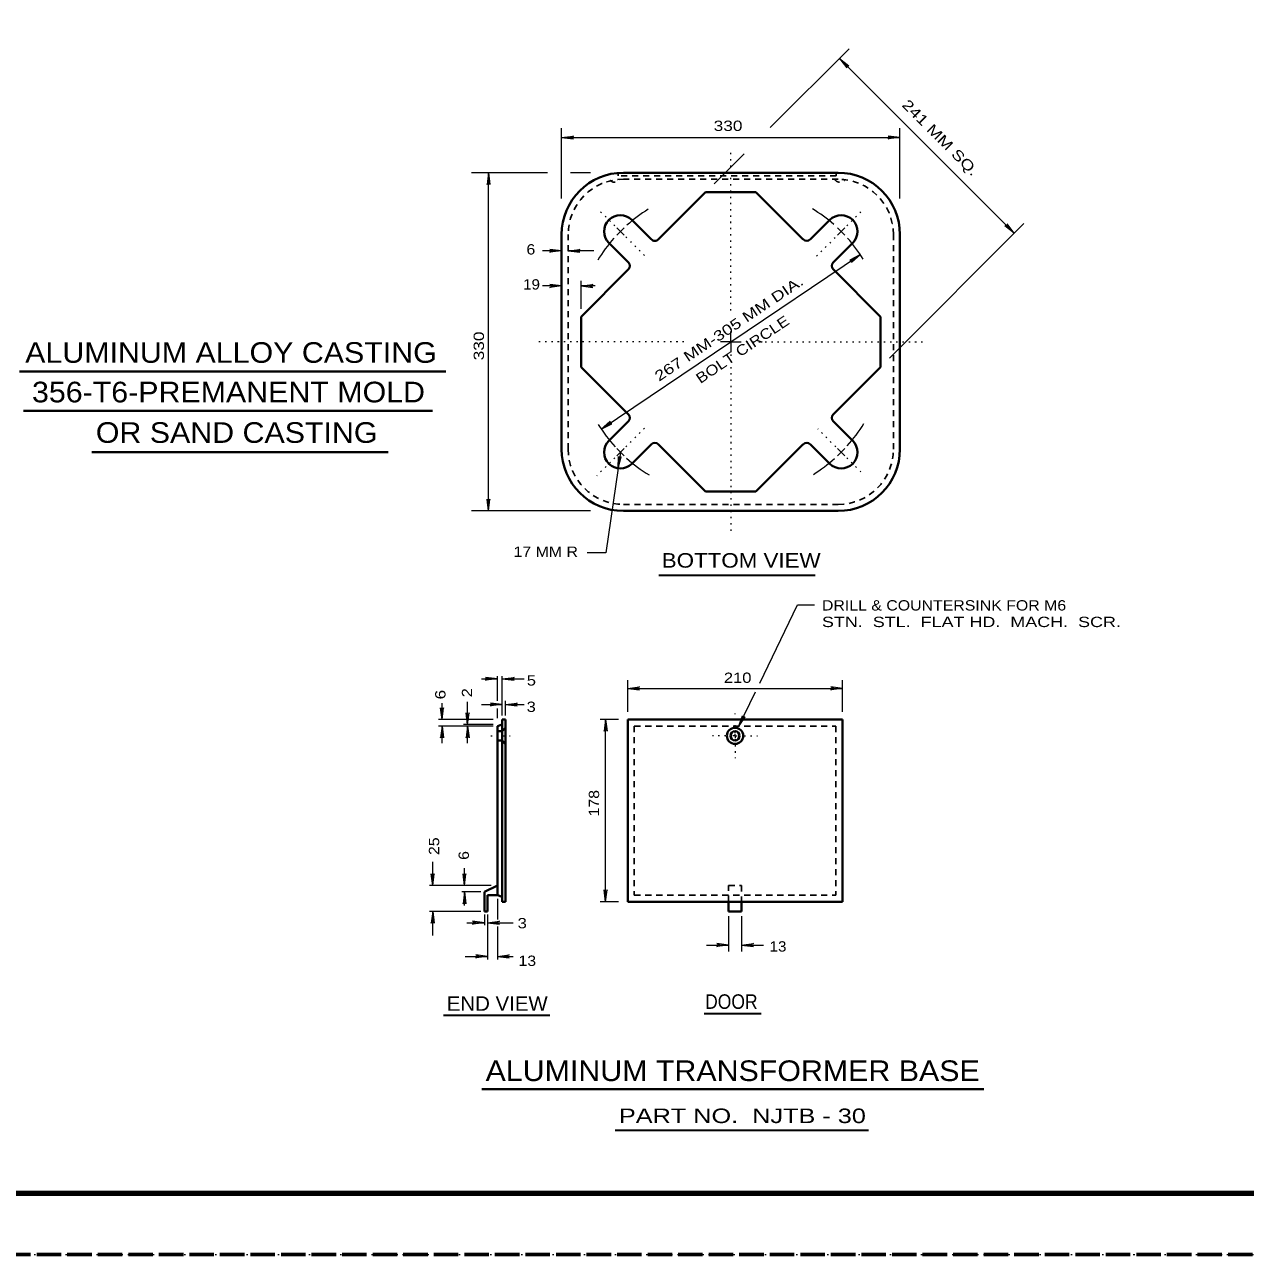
# Model space of a CAD drawing. Extents: x 312583 to 312854, y 144419 to 144597.
# Drawn here: x 312628.6 to 312718.5, y 144418.6 to 144509.2 of the extents above; entities that cross this region are included whole.
import ezdxf
from ezdxf.enums import TextEntityAlignment as Align

# ---------------------------------------------------------------- set-up
doc = ezdxf.new("R2010")
doc.units = 0
doc.header["$LTSCALE"] = 0.3
for name, pattern in [('DOTTED', [1.5, 0.3, -1.2]), ('LONG_DASHED', [7.5, 6, -1.5]), ('SHORT_DASHED', [2.7, 1.5, -1.2])]:
    doc.linetypes.add(name, pattern=pattern)
for name, color, linetype, lineweight in [('1', 7, 'Continuous', 40), ('2', 7, 'Continuous', 13), ('63', 7, 'DOTTED', 13)]:
    doc.layers.add(name, color=color, linetype=linetype, lineweight=lineweight)

msp = doc.modelspace()

# ---------------------------------------------------------------- linework, layer by layer
at = {"layer": '1', "linetype": 'SHORT_DASHED', "lineweight": 25}
for p, q in [((312672.2823, 144498.025), (312672.2823, 144498.2626)), ((312688.3363, 144498.025), (312688.3363, 144498.2626)), ((312688.3363, 144498.025), (312672.2823, 144498.025)), ((312688.482, 144497.7873), (312672.6656, 144497.7873)), ((312668.5946, 144477.9), (312668.5946, 144493.7086)), ((312692.553, 144477.9), (312692.553, 144493.7086)), ((312672.6656, 144473.829), (312688.482, 144473.829)), ((312673.463, 144457.499), (312673.463, 144445.0406)), ((312680.409, 144445.7613), (312681.3673, 144445.7613)), ((312680.409, 144444.5653), (312680.409, 144445.7613)), ((312681.3673, 144445.7613), (312681.3673, 144444.5653)), ((312673.463, 144445.0406), (312688.3133, 144445.0406))]:
    msp.add_line(p, q, dxfattribs=at)
at = {"layer": '1'}
for p, q in [((312688.482, 144498.2626), (312672.6656, 144498.2626)), ((312675.257, 144493.3636), (312678.7146, 144496.829)), ((312678.7146, 144496.829), (312682.4253, 144496.829)), ((312685.8906, 144493.3636), (312682.4253, 144496.829)), ((312673.2866, 144494.782), (312674.7126, 144493.3636)), ((312687.861, 144494.782), (312686.435, 144493.3636)), ((312668.1116, 144477.9), (312668.1116, 144493.7086)), ((312693.0283, 144477.9), (312693.0283, 144493.7086)), ((312671.5923, 144493.0876), (312673.0183, 144491.6693)), ((312689.5553, 144493.0876), (312688.1293, 144491.6693)), ((312669.553, 144487.6596), (312673.0183, 144491.125)), ((312691.5946, 144487.6596), (312688.1293, 144491.125)), ((312669.553, 144487.6596), (312669.553, 144483.949)), ((312691.5946, 144487.6596), (312691.5946, 144483.949)), ((312673.0183, 144480.4836), (312669.553, 144483.949)), ((312688.1293, 144480.4836), (312691.5946, 144483.949)), ((312671.5923, 144478.521), (312673.0183, 144479.947)), ((312689.5553, 144478.521), (312688.1293, 144479.9393)), ((312673.2866, 144476.8266), (312674.7126, 144478.2526)), ((312678.7146, 144474.7873), (312675.2493, 144478.2526)), ((312682.4253, 144474.7873), (312685.8906, 144478.245)), ((312687.861, 144476.8266), (312686.435, 144478.245)), ((312678.7146, 144474.7873), (312682.4253, 144474.7873)), ((312672.6656, 144473.346), (312688.482, 144473.346)), ((312663.3813, 144457.499), (312663.7416, 144457.6216)), ((312663.3813, 144445.0406), (312663.3813, 144457.499)), ((312663.9793, 144457.982), (312663.7416, 144457.982)), ((312663.7416, 144444.5653), (312663.7416, 144457.982)), ((312663.7416, 144457.1233), (312663.9793, 144457.384)), ((312663.9793, 144444.5653), (312663.9793, 144457.982)), ((312672.98, 144457.982), (312688.7963, 144457.982)), ((312672.98, 144457.982), (312672.98, 144444.5653)), ((312688.7963, 144457.982), (312688.7963, 144444.5653)), ((312663.7416, 144457.1233), (312663.3813, 144457.1233)), ((312663.734, 144456.4486), (312663.3813, 144456.4486)), ((312663.734, 144456.4486), (312663.9793, 144456.1803)), ((312662.423, 144445.286), (312663.3813, 144445.7613)), ((312662.423, 144443.8446), (312662.423, 144445.286)), ((312663.3813, 144445.0406), (312662.6606, 144445.0406)), ((312662.6606, 144443.8446), (312662.6606, 144445.0406)), ((312663.3813, 144445.0406), (312663.7416, 144444.9256)), ((312662.6606, 144443.8446), (312662.423, 144443.8446)), ((312663.9793, 144444.5653), (312663.7416, 144444.5653)), ((312672.98, 144444.5653), (312688.7963, 144444.5653)), ((312680.409, 144444.5653), (312680.409, 144443.8446)), ((312680.409, 144443.8446), (312681.3673, 144443.8446)), ((312681.3673, 144444.5653), (312681.3673, 144443.8446))]:
    msp.add_line(p, q, dxfattribs=at)
at = {"layer": '1', "linetype": 'DOTTED', "lineweight": 13}
msp.add_line((312662.8983, 144456.7783), (312664.3243, 144456.7783), dxfattribs=at)
at = {"layer": '1', "lineweight": 158}
msp.add_line((312616.5, 144423.0846), (312849, 144423.0846), dxfattribs=at)
at = {"layer": '1', "linetype": 'LONG_DASHED', "lineweight": 60}
msp.add_line((312851.75, 144418.5846), (312583.526, 144418.5846), dxfattribs=at)
at = {"layer": '1', "linetype": 'SHORT_DASHED', "lineweight": 25}
msp.add_lwpolyline([(312673.463, 144457.499), (312688.3133, 144457.499), (312688.3133, 144445.0406)], dxfattribs=at)
at = {"layer": '1'}
for radius in [0.599, 0.3369]:
    msp.add_circle((312680.8862, 144456.7841), radius, dxfattribs=at)
for centre, radius, start, end in [((312672.6656, 144493.7125), 4.5521, 90, 180), ((312688.4781, 144493.7125), 4.5521, 0, 90), ((312672.4395, 144493.9386), 1.1979, 45, 225), ((312688.7043, 144493.9386), 1.1979, 315, 135), ((312674.982, 144493.6326), 0.3833, 225, 315.01642), ((312686.1628, 144493.6336), 0.3833, 225, 315), ((312672.7445, 144491.3971), 0.3833, 315, 45), ((312688.3992, 144491.3971), 0.3833, 135, 225), ((312672.7445, 144480.2153), 0.3833, 315, 45), ((312688.4003, 144480.2142), 0.3833, 135.01744, 225), ((312672.4395, 144477.6738), 1.1979, 135, 315), ((312674.981, 144477.9789), 0.3833, 45, 135), ((312686.1638, 144477.9778), 0.3833, 45, 134.98307), ((312688.7043, 144477.6738), 1.1979, 225, 45), ((312672.6656, 144477.9), 4.5521, 180, 270), ((312688.4781, 144477.9), 4.5521, 270, 0)]:
    msp.add_arc(centre, radius, start, end, dxfattribs=at)
at = {"layer": '1', "linetype": 'SHORT_DASHED', "lineweight": 25}
for centre, radius, start, end in [((312672.6656, 144493.7125), 4.0729, 90, 180), ((312672.0061, 144498.0336), 0.4681, 222.5149, 327.98151), ((312688.6125, 144498.0336), 0.4681, 212.01849, 317.4851), ((312688.4781, 144493.7125), 4.0729, 0, 90), ((312672.6656, 144477.9), 4.0729, 180, 270), ((312688.4781, 144477.9), 4.0729, 270, 0)]:
    msp.add_arc(centre, radius, start, end, dxfattribs=at)
at = {"layer": '1', "lineweight": 13}
for start, end in [(121.91529, 131.69697), (48.74664, 58.47945), (138.46762, 148.47945), (31.91529, 41.61454), (211.91586, 222.30128), (318.2176, 328.47945), (228.10873, 238.48383), (301.91529, 311.69697)]:
    msp.add_arc((312680.5719, 144485.8062), 11.501, start, end, dxfattribs=at)
at = {"layer": '2'}
for p, q in [((312683.4756, 144501.59), (312689.287, 144507.3936)), ((312688.574, 144506.6806), (312701.454, 144493.8083)), ((312688.574, 144506.6806), (312689.1106, 144505.9983)), ((312688.574, 144506.6806), (312689.264, 144506.144)), ((312689.1106, 144505.9983), (312688.9956, 144506.2666)), ((312689.264, 144506.144), (312688.9956, 144506.2666)), ((312668.1116, 144496.3536), (312668.1116, 144501.5363)), ((312668.1116, 144500.8616), (312668.978, 144500.969)), ((312668.1116, 144500.8616), (312693.0283, 144500.8616)), ((312668.1116, 144500.8616), (312668.978, 144500.7543)), ((312668.978, 144500.969), (312668.702, 144500.8616)), ((312668.978, 144500.7543), (312668.702, 144500.8616)), ((312692.162, 144500.969), (312692.438, 144500.8616)), ((312693.0283, 144500.8616), (312692.162, 144500.969)), ((312692.162, 144500.7543), (312692.438, 144500.8616)), ((312693.0283, 144500.8616), (312692.162, 144500.7543)), ((312693.0283, 144496.3536), (312693.0283, 144501.5363)), ((312679.3433, 144497.45), (312681.559, 144499.6656)), ((312667.0766, 144498.2626), (312661.48, 144498.2626)), ((312662.7296, 144498.2626), (312662.6223, 144497.3963)), ((312662.7296, 144473.346), (312662.7296, 144498.2626)), ((312662.7296, 144498.2626), (312662.837, 144497.3963)), ((312670.2506, 144498.2626), (312668.771, 144498.2626)), ((312662.6223, 144497.3963), (312662.7296, 144497.6723)), ((312662.837, 144497.3963), (312662.7296, 144497.6723)), ((312692.2616, 144484.616), (312702.1593, 144494.5136)), ((312700.9173, 144494.4906), (312701.0323, 144494.2223)), ((312701.454, 144493.8083), (312700.9173, 144494.4906)), ((312672.4433, 144493.9386), (312672.1673, 144494.207)), ((312672.4433, 144493.9386), (312672.1673, 144493.6626)), ((312672.4433, 144493.9386), (312672.7116, 144494.207)), ((312672.4433, 144493.9386), (312672.7116, 144493.6626)), ((312688.7043, 144493.9386), (312688.436, 144494.207)), ((312688.7043, 144493.9386), (312688.436, 144493.6626)), ((312688.7043, 144493.9386), (312688.9803, 144494.207)), ((312688.7043, 144493.9386), (312688.9803, 144493.6626)), ((312700.764, 144494.345), (312701.0323, 144494.2223)), ((312701.454, 144493.8083), (312700.764, 144494.345)), ((312668.1116, 144492.5126), (312666.701, 144492.5126)), ((312667.2453, 144492.62), (312667.5213, 144492.5126)), ((312668.1116, 144492.5126), (312667.2453, 144492.62)), ((312667.2453, 144492.4053), (312667.5213, 144492.5126)), ((312668.1116, 144492.5126), (312667.2453, 144492.4053)), ((312668.5946, 144492.5126), (312669.461, 144492.62)), ((312670.496, 144492.5126), (312668.5946, 144492.5126)), ((312668.5946, 144492.5126), (312669.461, 144492.4053)), ((312669.461, 144492.62), (312669.185, 144492.5126)), ((312669.461, 144492.4053), (312669.185, 144492.5126)), ((312671.0326, 144479.3796), (312690.115, 144492.229)), ((312690.115, 144492.229), (312689.333, 144491.8303)), ((312689.333, 144491.8303), (312689.6243, 144491.8993)), ((312690.115, 144492.229), (312689.4556, 144491.654)), ((312689.4556, 144491.654), (312689.6243, 144491.8993)), ((312667.2453, 144490.0286), (312667.5213, 144489.9213)), ((312668.1116, 144489.9213), (312667.2453, 144490.0286)), ((312669.553, 144488.2346), (312669.553, 144490.297)), ((312669.553, 144489.9213), (312670.4193, 144490.0286)), ((312670.4193, 144490.0286), (312670.1433, 144489.9213)), ((312668.1116, 144489.9213), (312666.701, 144489.9213)), ((312667.2453, 144489.814), (312667.5213, 144489.9213)), ((312668.1116, 144489.9213), (312667.2453, 144489.814)), ((312670.5803, 144489.9213), (312669.553, 144489.9213)), ((312669.553, 144489.9213), (312670.4193, 144489.814)), ((312670.4193, 144489.814), (312670.1433, 144489.9213)), ((312680.57, 144485.8043), (312680.57, 144486.571)), ((312680.57, 144485.8043), (312679.8033, 144485.8043)), ((312680.57, 144485.8043), (312681.3366, 144485.8043)), ((312680.57, 144485.8043), (312680.57, 144485.0376)), ((312671.0326, 144479.3796), (312671.692, 144479.9546)), ((312671.0326, 144479.3796), (312671.8146, 144479.7783)), ((312671.692, 144479.9546), (312671.5233, 144479.7093)), ((312671.8146, 144479.7783), (312671.5233, 144479.7093)), ((312672.4433, 144477.67), (312671.3776, 144470.2563)), ((312672.4433, 144477.67), (312672.1673, 144477.946)), ((312672.4433, 144477.67), (312672.1673, 144477.4016)), ((312672.267, 144476.4893), (312672.29, 144477.3556)), ((312672.267, 144476.4893), (312672.497, 144477.325)), ((312672.29, 144477.3556), (312672.3513, 144477.072)), ((312672.497, 144477.325), (312672.3513, 144477.072)), ((312672.4433, 144477.67), (312672.7116, 144477.946)), ((312672.4433, 144477.67), (312672.7116, 144477.4016)), ((312688.7043, 144477.67), (312688.436, 144477.946)), ((312688.7043, 144477.67), (312688.436, 144477.4016)), ((312688.7043, 144477.67), (312688.9803, 144477.946)), ((312688.7043, 144477.67), (312688.9803, 144477.4016)), ((312662.6223, 144474.2123), (312662.7296, 144473.9363)), ((312662.7296, 144473.346), (312662.6223, 144474.2123)), ((312662.837, 144474.2123), (312662.7296, 144473.9363)), ((312662.7296, 144473.346), (312662.837, 144474.2123)), ((312670.2506, 144473.346), (312661.48, 144473.346)), ((312671.3776, 144470.2563), (312669.9823, 144470.2563)), ((312682.7115, 144460.6593), (312685.492, 144466.423)), ((312685.492, 144466.423), (312686.7493, 144466.423)), ((312662.216, 144460.9796), (312663.3813, 144460.9796)), ((312662.515, 144461.087), (312662.791, 144460.9796)), ((312663.3813, 144460.9796), (312662.515, 144461.087)), ((312662.515, 144460.8723), (312662.791, 144460.9796)), ((312663.3813, 144460.9796), (312662.515, 144460.8723)), ((312663.3813, 144459.362), (312663.3813, 144461.1866)), ((312663.7416, 144458.2886), (312663.7416, 144461.1866)), ((312663.7416, 144460.9796), (312664.608, 144461.087)), ((312663.7416, 144460.9796), (312665.3593, 144460.9796)), ((312663.7416, 144460.9796), (312664.608, 144460.8723)), ((312664.608, 144461.087), (312664.332, 144460.9796)), ((312664.608, 144460.8723), (312664.332, 144460.9796)), ((312672.98, 144458.5493), (312672.98, 144460.8723)), ((312672.98, 144460.2743), (312673.8463, 144460.3816)), ((312672.98, 144460.2743), (312688.7963, 144460.2743)), ((312672.98, 144460.2743), (312673.8463, 144460.167)), ((312673.8463, 144460.3816), (312673.5703, 144460.2743)), ((312673.8463, 144460.167), (312673.5703, 144460.2743)), ((312687.93, 144460.3816), (312688.206, 144460.2743)), ((312688.7963, 144460.2743), (312687.93, 144460.3816)), ((312687.93, 144460.167), (312688.206, 144460.2743)), ((312688.7963, 144460.2743), (312687.93, 144460.167)), ((312688.7963, 144458.5493), (312688.7963, 144460.8723)), ((312659.3103, 144457.982), (312659.3103, 144459.178)), ((312661.1886, 144457.6216), (312661.1886, 144459.293)), ((312662.8753, 144459.201), (312663.1513, 144459.0936)), ((312663.7416, 144459.0936), (312662.8753, 144459.201)), ((312663.9793, 144458.2886), (312663.9793, 144459.362)), ((312663.9793, 144459.0936), (312664.8456, 144459.201)), ((312664.8456, 144459.201), (312664.5696, 144459.0936)), ((312681.145, 144457.4453), (312682.3998, 144460.0191)), ((312659.203, 144458.8483), (312659.3103, 144458.5723)), ((312659.3103, 144457.982), (312659.203, 144458.8483)), ((312659.4176, 144458.8483), (312659.3103, 144458.5723)), ((312659.3103, 144457.982), (312659.4176, 144458.8483)), ((312661.0813, 144458.488), (312661.1886, 144458.212)), ((312661.1886, 144457.6216), (312661.0813, 144458.488)), ((312661.296, 144458.488), (312661.1886, 144458.212)), ((312661.1886, 144457.6216), (312661.296, 144458.488)), ((312662.216, 144459.0936), (312663.7416, 144459.0936)), ((312662.8753, 144458.9863), (312663.1513, 144459.0936)), ((312663.7416, 144459.0936), (312662.8753, 144458.9863)), ((312663.3813, 144458.0816), (312663.3813, 144458.7946)), ((312663.9793, 144459.0936), (312665.3593, 144459.0936)), ((312663.9793, 144459.0936), (312664.8456, 144458.9863)), ((312664.8456, 144458.9863), (312664.5696, 144459.0936)), ((312681.145, 144457.4453), (312681.4286, 144458.2656)), ((312681.4286, 144458.2656), (312681.4056, 144457.9743)), ((312663.0823, 144457.982), (312659.042, 144457.982)), ((312663.0823, 144457.499), (312659.042, 144457.499)), ((312659.3103, 144457.499), (312659.203, 144456.6326)), ((312659.3103, 144456.2493), (312659.3103, 144457.499)), ((312659.3103, 144457.499), (312659.4176, 144456.6326)), ((312663.0823, 144457.6216), (312660.8743, 144457.6216)), ((312661.1886, 144457.499), (312661.0813, 144456.6326)), ((312661.1886, 144456.2493), (312661.1886, 144457.499)), ((312661.1886, 144457.499), (312661.296, 144456.6326)), ((312672.313, 144457.982), (312670.9406, 144457.982)), ((312671.3546, 144457.982), (312671.2473, 144457.1156)), ((312671.2473, 144457.1156), (312671.3546, 144457.3916)), ((312671.3546, 144444.5653), (312671.3546, 144457.982)), ((312671.3546, 144457.982), (312671.462, 144457.1156)), ((312671.462, 144457.1156), (312671.3546, 144457.3916)), ((312681.145, 144457.4453), (312681.6203, 144458.1736)), ((312681.6203, 144458.1736), (312681.4056, 144457.9743)), ((312659.203, 144456.6326), (312659.3103, 144456.9086)), ((312659.4176, 144456.6326), (312659.3103, 144456.9086)), ((312661.0813, 144456.6326), (312661.1886, 144456.9086)), ((312661.296, 144456.6326), (312661.1886, 144456.9086)), ((312680.8843, 144456.786), (312680.7463, 144456.786)), ((312680.8843, 144456.786), (312680.8843, 144456.924)), ((312680.8843, 144456.786), (312681.03, 144456.786)), ((312680.8843, 144456.786), (312680.8843, 144456.6403)), ((312658.6203, 144445.7613), (312658.6203, 144447.5093)), ((312658.513, 144446.6276), (312658.6203, 144446.3516)), ((312658.6203, 144445.7613), (312658.513, 144446.6276)), ((312658.7276, 144446.6276), (312658.6203, 144446.3516)), ((312658.6203, 144445.7613), (312658.7276, 144446.6276)), ((312660.8513, 144446.6276), (312660.9586, 144446.3516)), ((312660.9586, 144445.7613), (312660.8513, 144446.6276)), ((312660.9586, 144445.7613), (312660.9586, 144447.034)), ((312661.066, 144446.6276), (312660.9586, 144446.3516)), ((312660.9586, 144445.7613), (312661.066, 144446.6276)), ((312662.9213, 144445.7613), (312658.375, 144445.7613)), ((312662.17, 144445.286), (312660.767, 144445.286)), ((312660.9586, 144445.286), (312660.8513, 144444.4196)), ((312660.8513, 144444.4196), (312660.9586, 144444.6956)), ((312660.9586, 144444.2893), (312660.9586, 144445.286)), ((312660.9586, 144445.286), (312661.066, 144444.4196)), ((312661.066, 144444.4196), (312660.9586, 144444.6956)), ((312663.3813, 144444.7723), (312663.3813, 144443.2466)), ((312671.2473, 144445.4316), (312671.3546, 144445.1556)), ((312671.3546, 144444.5653), (312671.2473, 144445.4316)), ((312671.462, 144445.4316), (312671.3546, 144445.1556)), ((312671.3546, 144444.5653), (312671.462, 144445.4316)), ((312662.17, 144443.8446), (312658.375, 144443.8446)), ((312658.6203, 144443.8446), (312658.513, 144442.9783)), ((312658.6203, 144442.0813), (312658.6203, 144443.8446)), ((312658.6203, 144443.8446), (312658.7276, 144442.9783)), ((312672.313, 144444.5653), (312670.9406, 144444.5653)), ((312658.513, 144442.9783), (312658.6203, 144443.2543)), ((312658.7276, 144442.9783), (312658.6203, 144443.2543)), ((312661.1426, 144443.0166), (312662.423, 144443.0166)), ((312661.5566, 144443.124), (312661.8326, 144443.0166)), ((312662.423, 144443.0166), (312661.5566, 144443.124)), ((312661.5566, 144442.9093), (312661.8326, 144443.0166)), ((312662.423, 144443.0166), (312661.5566, 144442.9093)), ((312662.423, 144443.6146), (312662.423, 144442.8326)), ((312662.6606, 144443.6146), (312662.6606, 144440.318)), ((312662.6606, 144443.0166), (312663.527, 144443.124)), ((312662.6606, 144443.0166), (312664.5466, 144443.0166)), ((312662.6606, 144443.0166), (312663.527, 144442.9093)), ((312663.527, 144443.124), (312663.251, 144443.0166)), ((312663.527, 144442.9093), (312663.251, 144443.0166)), ((312680.409, 144443.4996), (312680.409, 144440.9006)), ((312681.3673, 144443.4996), (312681.3673, 144440.9006)), ((312663.3813, 144442.733), (312663.3813, 144440.318)), ((312678.7836, 144441.3683), (312680.409, 144441.3683)), ((312679.5426, 144441.4756), (312679.8186, 144441.3683)), ((312680.409, 144441.3683), (312679.5426, 144441.4756)), ((312679.5426, 144441.261), (312679.8186, 144441.3683)), ((312680.409, 144441.3683), (312679.5426, 144441.261)), ((312681.3673, 144441.3683), (312682.2336, 144441.4756)), ((312681.3673, 144441.3683), (312682.9773, 144441.3683)), ((312681.3673, 144441.3683), (312682.2336, 144441.261)), ((312682.2336, 144441.4756), (312681.9576, 144441.3683)), ((312682.2336, 144441.261), (312681.9576, 144441.3683)), ((312661.0046, 144440.5403), (312662.6606, 144440.5403)), ((312661.7943, 144440.6476), (312662.0703, 144440.5403)), ((312662.6606, 144440.5403), (312661.7943, 144440.6476)), ((312661.7943, 144440.433), (312662.0703, 144440.5403)), ((312662.6606, 144440.5403), (312661.7943, 144440.433)), ((312663.3813, 144440.5403), (312664.2476, 144440.6476)), ((312663.3813, 144440.5403), (312664.5466, 144440.5403)), ((312663.3813, 144440.5403), (312664.2476, 144440.433)), ((312664.2476, 144440.6476), (312663.9716, 144440.5403)), ((312664.2476, 144440.433), (312663.9716, 144440.5403))]:
    msp.add_line(p, q, dxfattribs=at)
at = {"layer": '2', "linetype": 'DOTTED'}
for p, q in [((312680.57, 144488.1196), (312680.57, 144500.049)), ((312672.037, 144494.345), (312670.749, 144495.6253)), ((312689.1106, 144494.345), (312690.2836, 144495.5103)), ((312672.8496, 144493.5323), (312674.4136, 144491.9683)), ((312688.252, 144493.4786), (312686.757, 144491.9913)), ((312677.12, 144485.8043), (312666.4403, 144485.8043)), ((312681.72, 144485.8043), (312694.7456, 144485.8043)), ((312680.57, 144484.869), (312680.57, 144471.6363)), ((312672.8496, 144478.0763), (312674.2603, 144479.487)), ((312688.298, 144478.0763), (312686.9946, 144479.3873)), ((312672.037, 144477.2636), (312670.703, 144475.9373)), ((312689.1106, 144477.2636), (312690.276, 144476.106)), ((312680.8843, 144457.0006), (312680.8843, 144458.4343)), ((312680.6696, 144456.786), (312679.236, 144456.786)), ((312680.8843, 144456.5636), (312680.8843, 144455.13)), ((312681.1066, 144456.786), (312682.5403, 144456.786))]:
    msp.add_line(p, q, dxfattribs=at)
at = {"layer": '2', "lineweight": 40}
for p, q in [((312628.1899, 144483.6301), (312659.5842, 144483.6301)), ((312628.4734, 144480.7223), (312658.5921, 144480.7223)), ((312633.505, 144477.6726), (312655.3322, 144477.6726)), ((312662.2239, 144430.7653), (312699.2168, 144430.7653))]:
    msp.add_line(p, q, dxfattribs=at)
at = {"layer": '2', "lineweight": 35}
for p, q in [((312675.2787, 144468.631), (312686.7947, 144468.631)), ((312659.4156, 144436.201), (312667.2464, 144436.201)), ((312678.6207, 144436.331), (312682.8019, 144436.331)), ((312672.047, 144427.7338), (312690.7206, 144427.7338))]:
    msp.add_line(p, q, dxfattribs=at)
at = {"layer": '63'}
msp.add_lwpolyline([(312601.2, 144418.5846), (312853.5, 144418.5846), (312853.5, 144596.7846)], dxfattribs=at)

# ---------------------------------------------------------------- texts
at = {"layer": '2'}
for s, rotation, width, p in [('241 MM SQ.', 315, 1.3, (312693.1158, 144503.2061)), ('267 MM-305 MM DIA.', 33.952, 1.3, (312675.2878, 144482.8606)), ('BOLT CIRCLE', 33.952, 1.2, (312678.3319, 144482.6973)), ('330 ', 90, 1.25, (312662.3918, 144484.4466)), (' 6 ', 90, 1.25, (312659.5589, 144459.1127)), (' 2 ', 90, 1.2, (312661.5234, 144459.2795)), ('178 ', 90, 1.15, (312670.8751, 144450.8443)), ('25 ', 90, 1.15, (312659.0931, 144448.0039)), ('6 ', 90, 1.15, (312661.2839, 144447.6473))]:
    msp.add_text(s, height=0.76, rotation=rotation, dxfattribs=dict(at, width=width)).set_placement(p)
for s, width, p in [('330 ', 1.25, (312679.3116, 144501.3417)), ('6 ', 1.15, (312665.5224, 144492.2396)), ('19 ', 1.1, (312665.2732, 144489.6578)), ('17 MM R', 1.15, (312664.5721, 144469.9678)), ('DRILL & COUNTERSINK FOR M6', 1.15, (312687.286, 144466.0156)), ('STN.  STL.  FLAT HD.  MACH.  SCR.', 1.3, (312687.286, 144464.7956)), (' 5 ', 1.2, (312665.2082, 144460.488)), ('210 ', 1.2, (312680.0603, 144460.6835)), (' 3 ', 1.2, (312665.1929, 144458.5464)), (' 3 ', 1.2, (312664.5316, 144442.6036)), ('13 ', 1.1, (312683.4276, 144440.892)), (' 13 ', 1.15, (312664.6081, 144439.8359))]:
    msp.add_text(s, height=0.76, dxfattribs=dict(at, width=width)).set_placement(p)
for s, height, width, p in [('ALUMINUM ALLOY CASTING', 1.52, 1.1, (312643.7599, 144484.2614)), ('356-T6-PREMANENT MOLD', 1.52, 1.1, (312643.5756, 144481.3481)), ('OR SAND CASTING', 1.52, 1.1, (312644.1765, 144478.3657)), ('BOTTOM VIEW ', 1.07, 1.15, (312681.5667, 144469.1731)), ('END VIEW', 1.07, 1.05, (312663.3713, 144436.5303)), ('DOOR', 1.07, 0.9, (312680.6123, 144436.6722)), ('ALUMINUM TRANSFORMER BASE', 1.52, 1.1, (312680.7106, 144431.3539)), ('PART NO.  NJTB - 30', 1.07, 1.3, (312681.4262, 144428.258))]:
    msp.add_text(s, height=height, dxfattribs=dict(at, width=width)).set_placement(p, align=Align.CENTER)

doc.saveas('drawing.dxf')
